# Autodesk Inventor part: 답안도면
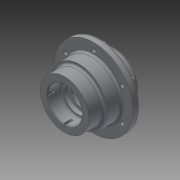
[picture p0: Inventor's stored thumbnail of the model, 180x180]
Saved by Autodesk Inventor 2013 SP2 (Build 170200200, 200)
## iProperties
Created: 2024-04
Part Number: 답안도면
Material: Generic
Document SubType Name: Modeling
Designer: a
Density: 1 g/cm^3
Author: a
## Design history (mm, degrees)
sketch "스케치1"
  geometry: C1 r 54.5 at (0, 0); 1 further point
  constraints: 1 centre point, 1 coincident
  dimensions: "d0" = 109 diameter of C1
extrude "돌출1" new body sketch "스케치1" distance "d2" = 10; taper "d3" = 0 deg
sketch "스케치2"
  geometry: C1 r 54.5 at (0, 0) reference; C2 r 38.5 at (0, 0)
  constraints: 1 centre point, 1 coincident
  dimensions: "d4" = 77 diameter of C2
extrude "돌출2" join sketch "스케치2" distance "d6" = 20; taper "d7" = 0 deg
sketch "스케치3"
  geometry: C1 r 38.5 at (0, 0) reference; C2 r 33.5 at (0, 0)
  constraints: 1 centre point, 1 coincident
  dimensions: "d8" = 67 diameter of C2
extrude "돌출3" join sketch "스케치3" distance "d11" = 20; taper "d12" = 0 deg
fillet "모깎기1" dims "d13" = 3
sketch "스케치4"
  geometry: C1 r 33.5 at (0, 0) reference; C2 r 23.5 at (0, 0)
  constraints: 1 centre point, 1 coincident
  dimensions: "d14" = 47 diameter of C2
extrude "돌출4" cut sketch "스케치4" distance "d16" = 18; taper "d17" = 0 deg
sketch "스케치5"
  geometry: C1 r 23.5 at (0, 0) reference; C2 r 20.5 at (0, 0)
  constraints: 1 centre point, 1 coincident
  dimensions: "d18" = 41 diameter of C2
extrude "돌출5" cut sketch "스케치5" distance "d21" = 6; taper "d22" = 0 deg
sketch "스케치6"
  geometry: C1 r 54.5 at (0, 0) reference; C2 r 23.5 at (0, 0)
  constraints: 1 centre point, 1 coincident
  dimensions: "d23" = 47 diameter of C2
extrude "돌출6" cut sketch "스케치6" distance "d25" = 18; taper "d26" = 0 deg
sketch "스케치7"
  geometry: C1 r 23.5 at (0, 0) reference; C2 r 20.5 at (0, 0)
  constraints: 1 centre point, 1 coincident
  dimensions: "d27" = 41 diameter of C2
extrude "돌출7" cut sketch "스케치7" distance "d30" = 6; taper "d31" = 0 deg
sketch "스케치8"
  geometry: C1 r 20.5 at (0, 0) reference; C2 r 16 at (0, 0)
  constraints: 1 centre point, 1 coincident
  dimensions: "d32" = 32 diameter of C2
extrude "돌출8" cut sketch "스케치8" stored distance "d34" = 6; taper "d35" = 0 deg
sketch "스케치9"
  geometry: C1 r 23.5 at (0, 0) reference; C2 r 54.5 at (0, 0) reference; C3 r 25.5 at (0, 0)
  constraints: 1 centre point, 1 coincident
  dimensions: "d36" = 51 diameter of C3
extrude "돌출9" join sketch "스케치9" distance "d38" = 6; taper "d39" = 0 deg
sketch "스케치10"
  geometry: C1 r 54.5 at (0, 0) reference; C2 r 33.5 at (0, 0); 1 further point
  constraints: 1 centre point, 1 coincident, 1 vertical alignment, 1 other
  dimensions: "d40" = 67 diameter of C2; "d45" = 6 distance of C1.centre point (0, 6)
extrude "돌출10" join sketch "스케치10" distance "d42" = 20; taper "d43" = 0 deg
fillet "모깎기2" dims "d44" = 3
fillet "모깎기3" dims "d106" = 3
fillet "모깎기4" dims "d107" = 3
sketch "스케치14"
  geometry: C1 r 36.5 at (0, 0) reference; C2 r 3.5 at (0, 45); C3 r 3.5 at (-38.971, 22.5); C4 r 3.5 at (-38.971, -22.5); C5 r 3.5 at (0, -45); C6 r 3.5 at (38.971, -22.5); C7 r 3.5 at (38.971, 22.5)
  constraints: 6 centre point, 1 vertical alignment, 13 other
  dimensions: "d108" = 45 distance of C1.centre C2.centre; "d109" = 7 diameter of C2; "d112" = 360 deg dimension on C1.centre C2.centre (derived)
extrude "돌출13" join sketch "스케치14" distance "d114" = 5; taper "d115" = 0 deg
sketch "스케치16"
  geometry: C1 r 30.5 at (0, 0) reference; C2 r 23.5 at (0, 0)
  constraints: 1 centre point, 1 coincident
  dimensions: "d131" = 47 diameter of C2
extrude "돌출14" cut sketch "스케치16" distance "d133" = 18; taper "d134" = 0 deg
sketch "스케치17"
  geometry: C1 r 23.5 at (0, 0) reference; C2 r 16 at (0, 0)
  constraints: 1 centre point, 1 coincident
  dimensions: "d135" = 32 diameter of C2
extrude "돌출15" cut sketch "스케치17" distance "d137" = 6; taper "d138" = 0 deg
fillet "모깎기5" dims "d146" = 3
chamfer "모따기1" distance "d147" = 1; stored, may be unused: second distance "d148" = 2, angle "d149" = 45 deg
sketch "스케치20" dims "d151" = 47
  geometry: C1 r 54.5 at (0, 0) reference; C2 r 41.5 at (0, 0) reference; 8 further points
  constraints: 3 coincident, 3 vertical alignment, 2 horizontal alignment, 19 other
  dimensions: "d155" = 360 deg dimension on point (0, 0) point (0, 23.5) (derived)
hole "구멍8" sketch "스케치20" at (0, 23.5), (-23.5, 0), (0, -23.5), (23.5, 0) diameter "d157" = 3.242; stored, may be unused: countersink angle "d161" = 90 deg, drill point angle "d163" = 118 deg; dims "d158" = 8, "d159" = 4, "d160" = 2, "d162" = 10
fillet "모깎기6" dims "d164" = 1
fillet "모깎기7" dims "d165" = 1
chamfer "모따기2" distance "d166" = 0.6; stored, may be unused: second distance "d167" = 2, angle "d168" = 45 deg
sketch "스케치21" dims "d169" = 47
  geometry: C1 r 33.5 at (0, 0) reference; C2 r 24.5 at (0, 0) reference; 5 further points
  constraints: 2 vertical alignment, 1 coincident, 7 other
  dimensions: "d173" = 360 deg dimension on point (0, 0) point (0, 23.5) (derived)
hole "구멍9" sketch "스케치21" at (0, 23.5), (-23.5, 0), (0, -23.5), (23.5, 0) diameter "d175" = 3.242; stored, may be unused: countersink angle "d179" = 90 deg, drill point angle "d181" = 118 deg; dims "d176" = 8, "d177" = 4, "d178" = 2, "d180" = 10
hole "구멍10" diameter "d184" = 6; stored, may be unused: countersink angle "d188" = 90 deg, drill point angle "d190" = 0 deg; dims "d182" = 10, "d183" = 10, "d185" = 8, "d186" = 4, "d187" = 2, "d189" = 10
hole "구멍11" diameter "d193" = 6; stored, may be unused: countersink angle "d197" = 90 deg, drill point angle "d199" = 0 deg; dims "d191" = 10, "d192" = 10, "d194" = 8, "d195" = 4, "d196" = 2, "d198" = 10
hole "구멍12" diameter "d202" = 6; stored, may be unused: countersink angle "d206" = 90 deg, drill point angle "d208" = 0 deg; dims "d200" = 10, "d201" = 10, "d203" = 8, "d204" = 4, "d205" = 2, "d207" = 10
hole "구멍13" diameter "d211" = 6; stored, may be unused: countersink angle "d215" = 90 deg, drill point angle "d217" = 0 deg; dims "d209" = 10, "d210" = 10, "d212" = 8, "d213" = 4, "d214" = 2, "d216" = 10
hole "구멍14" diameter "d220" = 6; stored, may be unused: countersink angle "d224" = 90 deg, drill point angle "d226" = 0 deg; dims "d218" = 10, "d219" = 10, "d221" = 8, "d222" = 4, "d223" = 2, "d225" = 10
hole "구멍15" diameter "d229" = 6; stored, may be unused: countersink angle "d233" = 90 deg, drill point angle "d235" = 0 deg; dims "d227" = 10, "d228" = 10, "d230" = 8, "d231" = 4, "d232" = 2, "d234" = 10
node "솔리드1"
